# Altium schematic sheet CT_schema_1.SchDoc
size 390 x 339 mm
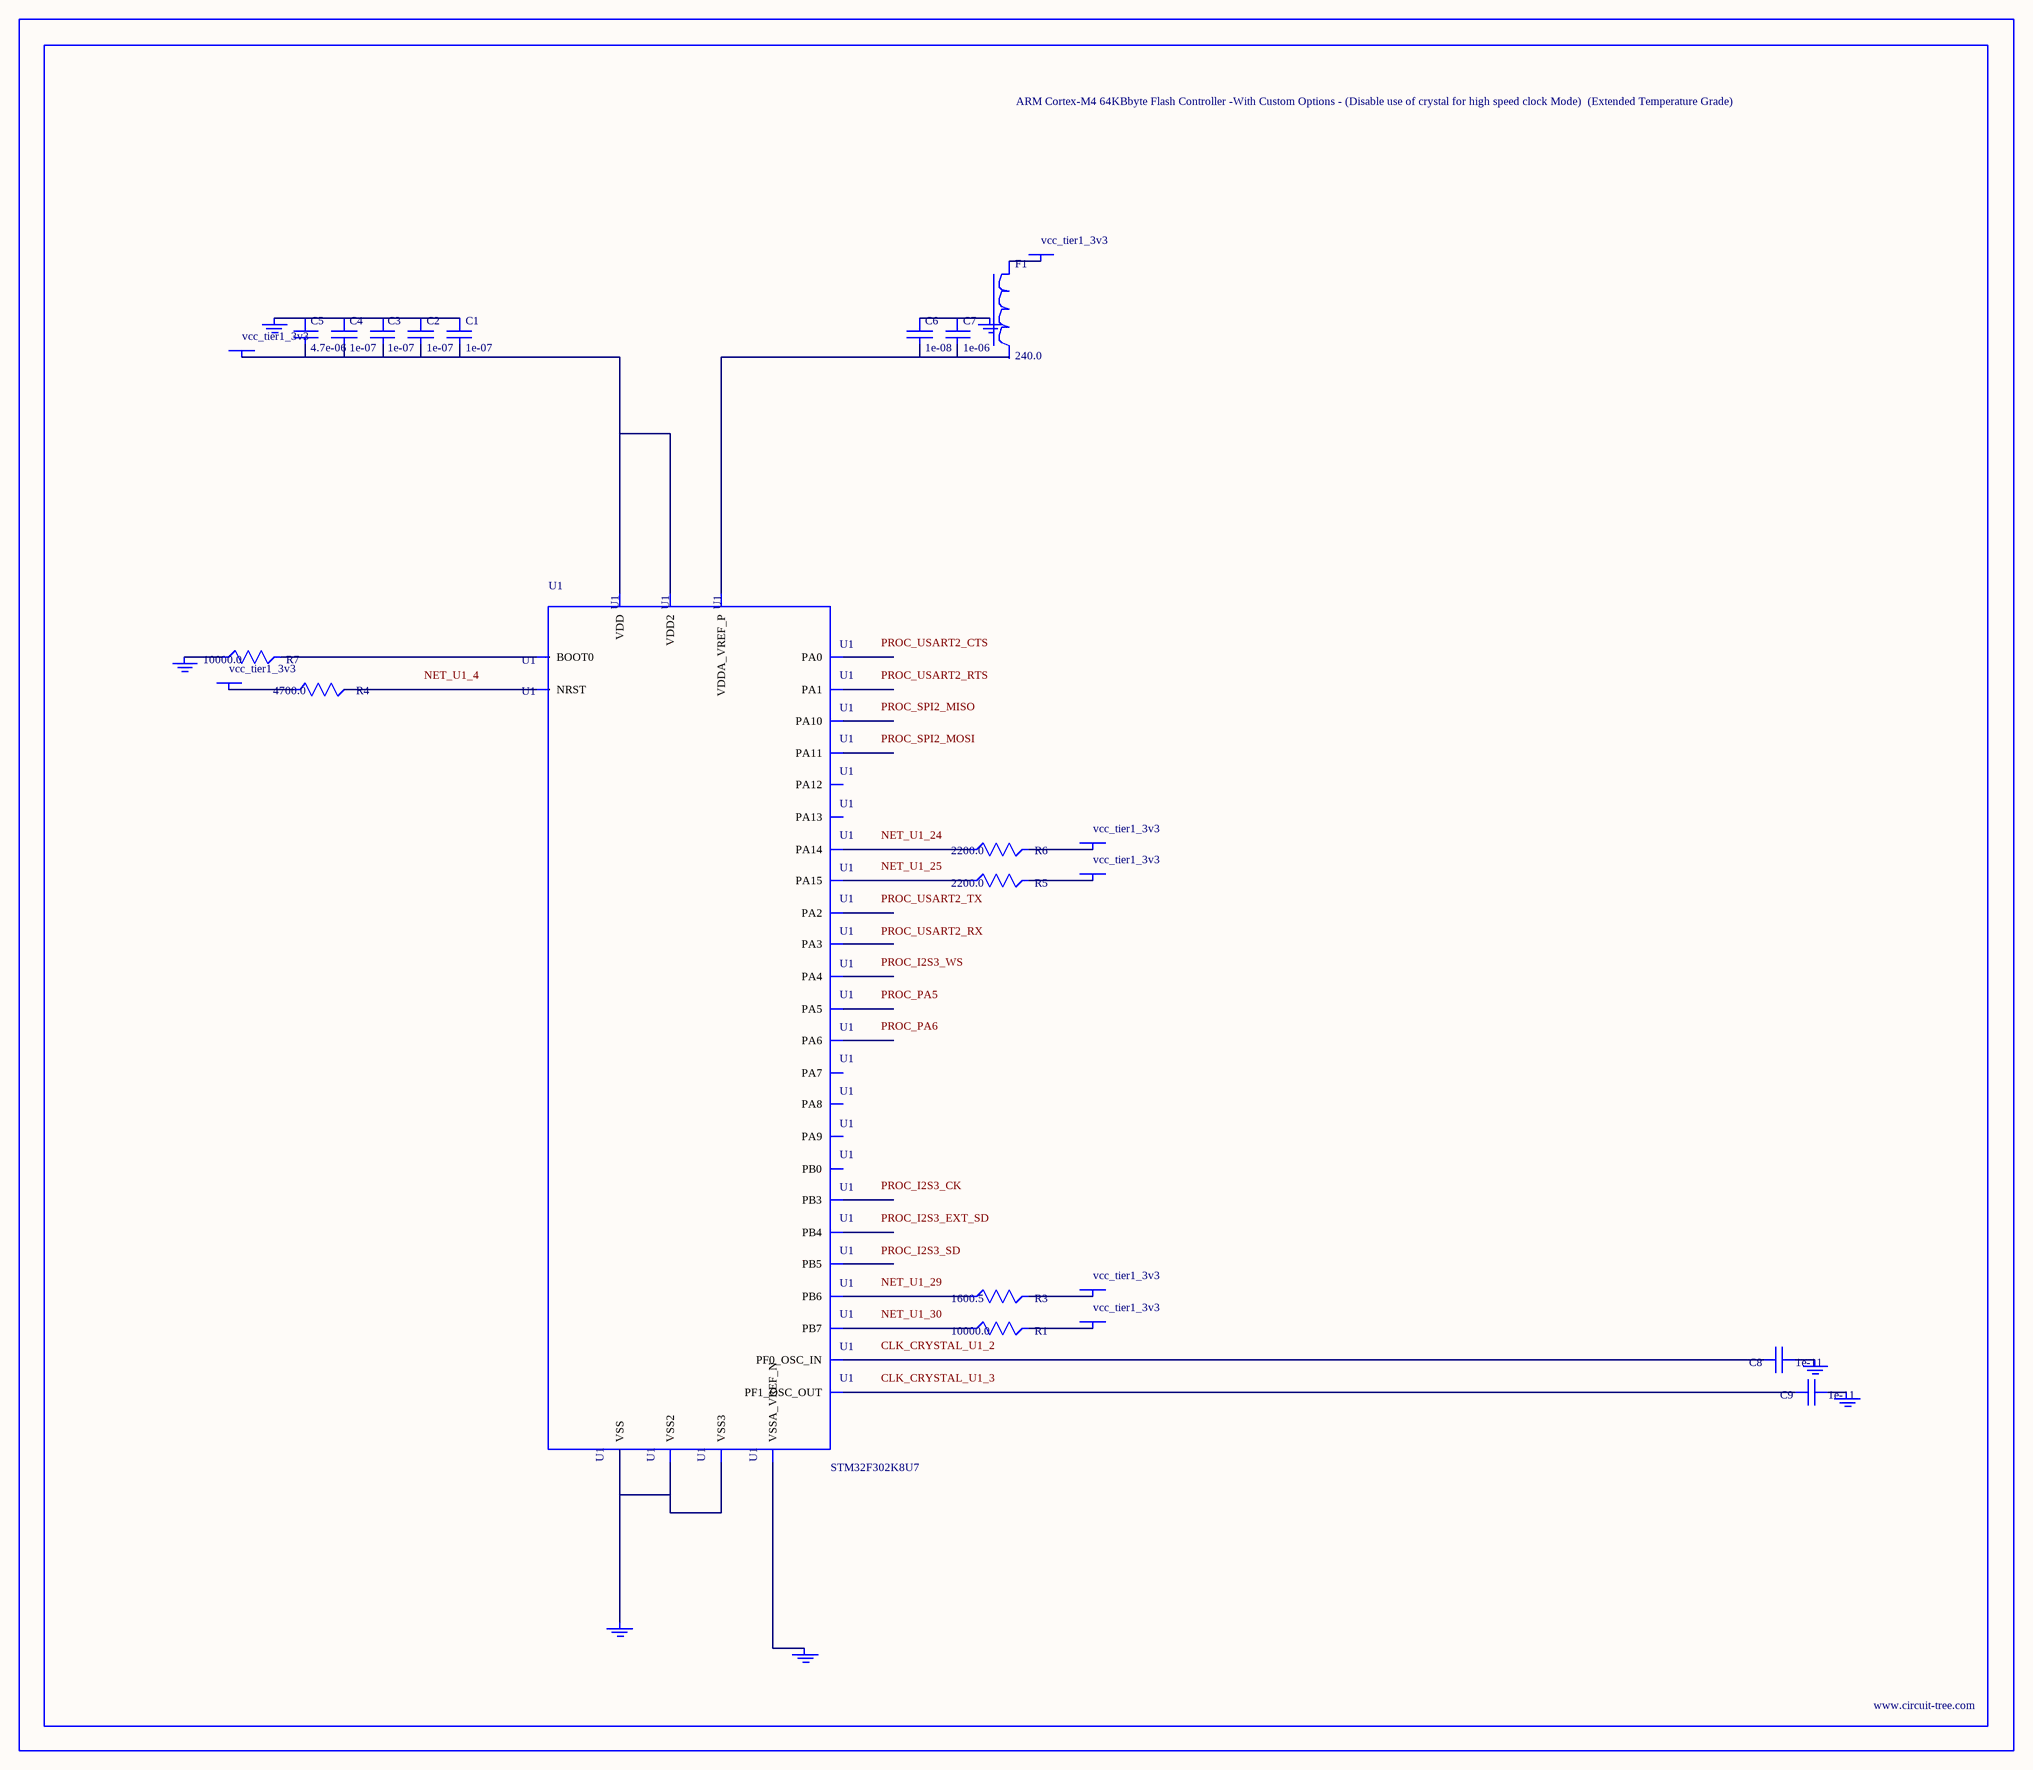
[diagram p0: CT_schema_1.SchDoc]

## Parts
BORDER0  (no value)
C1  1e-07  [C0603]
C2  1e-07  [C0603]
C3  1e-07  [C0603]
C4  1e-07  [C0603]
C5  4.7e-06  [C0603]
C6  1e-08  [C0603]
C7  1e-06  [C0603]
C8  1e-11  [C0402]
C9  1e-11  [C0402]
F1  240.0  [L0603]
GND_INSTANCE_0_0  (no value)
GND_INSTANCE_0_1  (no value)
GND_INSTANCE_0_2  (no value)
GND_INSTANCE_0_3  (no value)
GND_INSTANCE_0_4  (no value)
GND_INSTANCE_0_5  (no value)
GND_INSTANCE_0_6  (no value)
POWER_INSTANCE_0_0  vcc_tier1_3v3
POWER_INSTANCE_0_1  vcc_tier1_3v3
POWER_INSTANCE_0_2  vcc_tier1_3v3
POWER_INSTANCE_0_3  vcc_tier1_3v3
POWER_INSTANCE_0_4  vcc_tier1_3v3
POWER_INSTANCE_0_5  vcc_tier1_3v3
POWER_INSTANCE_0_6  vcc_tier1_3v3
R1  10000.0  [R0603]
R3  1600.5  [R0603]
R4  4700.0  [R0603]
R5  2200.0  [R0603]
R6  2200.0  [R0603]
R7  10000.0  [R0603]
U1  STM32F302K8U7  [UFQFPN32]

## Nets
NetC1_1: C1.1 C2.1 C3.1 C4.1 C5.1 GND_INSTANCE_0_0.0(GND)
NetC1_2: C1.2 C2.2 C3.2 C4.2 C5.2 POWER_INSTANCE_0_0.0(PWR) U1.1(VDD) U1.17(VDD2)
NetC6_1: C6.1 C7.1 GND_INSTANCE_0_3.0(GND)
NetC6_2: C6.2 C7.2 U1.5(VDDA_VREF_P)
NetC8_1: C8.1 GND_INSTANCE_0_1.0(GND)
NetC8_2: C8.2 U1.2(PF0_OSC_IN)
NetC9_1: C9.1 GND_INSTANCE_0_2.0(GND)
NetC9_2: C9.2 U1.3(PF1_OSC_OUT)
NetF1_1: F1.1 POWER_INSTANCE_0_1.0(PWR)
NetGND_INSTANCE_0_4_0: GND_INSTANCE_0_4.0(GND) U1.6(VSSA_VREF_N)
NetGND_INSTANCE_0_5_0: GND_INSTANCE_0_5.0(GND) R7.1
NetGND_INSTANCE_0_6_0: GND_INSTANCE_0_6.0(GND) U1.16(VSS) U1.32(VSS2) U1.EPAD(VSS3)
NetPOWER_INSTANCE_0_2_0: POWER_INSTANCE_0_2.0(PWR) R4.1
NetPOWER_INSTANCE_0_3_0: POWER_INSTANCE_0_3.0(PWR) R6.2
NetPOWER_INSTANCE_0_4_0: POWER_INSTANCE_0_4.0(PWR) R5.2
NetPOWER_INSTANCE_0_5_0: POWER_INSTANCE_0_5.0(PWR) R3.2
NetPOWER_INSTANCE_0_6_0: POWER_INSTANCE_0_6.0(PWR) R1.2
NetR1_1: R1.1 U1.30(PB7)
NetR3_1: R3.1 U1.29(PB6)
NetR4_2: R4.2 U1.4(NRST)
NetR5_1: R5.1 U1.25(PA15)
NetR6_1: R6.1 U1.24(PA14)
NetR7_2: R7.2 U1.31(BOOT0)

Not connected (* = marked no-connect by the designer): F1 2; U1 7(PA0) 8(PA1) 9(PA2) 10(PA3) 11(PA4) 12(PA5) 13(PA6) 14(PA7) 15(PB0) 18(PA8) 19(PA9) 20(PA10) 21(PA11) 22(PA12) 23(PA13) 26(PB3) 27(PB4) 28(PB5)

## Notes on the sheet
- Labels drawn without touching a wire or pin: CLK_CRYSTAL_U1_2, CLK_CRYSTAL_U1_3, NET_U1_4, NET_U1_24, NET_U1_25, NET_U1_29, NET_U1_30, PROC_I2S3_CK, PROC_I2S3_EXT_SD, PROC_I2S3_SD, PROC_I2S3_WS, PROC_PA5, PROC_PA6, PROC_SPI2_MISO, PROC_SPI2_MOSI, PROC_USART2_CTS, PROC_USART2_RTS, PROC_USART2_RX, PROC_USART2_TX

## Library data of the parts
BORDER0 = BORDER_PAGE0
C1-C4 = 06035C104K4Z2A
C5 = GRM188R6YA475KE15D
C6 = 06035C103K4Z2A
C7 = C0603C105K3RACTU
C8 C9 = C0402C100K3GACTU
F1 = Z0603C241ASMST
GND_INSTANCE_0_0-GND_INSTANCE_0_6 = GND
POWER_INSTANCE_0_0-POWER_INSTANCE_0_6 = PWR
R1 R7 = RC0603JR-0710KL
R3 = R3
R4 = RC0603JR-074K7L
R5 R6 = RC0603JR-072K2L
